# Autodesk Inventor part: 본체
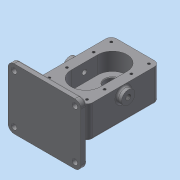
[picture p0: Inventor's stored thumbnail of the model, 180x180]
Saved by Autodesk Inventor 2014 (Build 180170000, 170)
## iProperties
Created: 2026-10
Part Number: 본체
Material: 일반
Document SubType Name: Modeling
Designer: dg
Density: 1 g/cm^3
Appearance: 기본값
Author: dg
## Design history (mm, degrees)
sketch "스케치1"
  geometry: L1 (-40, 60)-(40, 60); L2 (40, 60)-(40, -60); L3 (40, -60)-(-40, -60); L4 (-40, -60)-(-40, 60); L5 (0, 22)-(0, -22); L6 (-24, 22)-(-24, -22); L7 (24, -22)-(24, 22); A1 r 24 centre (0, 22) between (24, 22) and (-24, 22); A2 r 24 centre (0, -22) between (-24, -22) and (24, -22); 4 further points
  constraints: 16 end point, 4 parallel, 4 point on circle, 4 tangent, 3 midpoint, 2 centre point, 1 coincident, 1 horizontal, 1 horizontal alignment, 1 perpendicular, 1 vertical alignment
  dimensions: "d0" = 80 distance of L1.start L1.end; "d1" = 120 distance of L1.end L2.end; "d2" = 44 distance of L5.start L5.end; "d3" = 48 diameter of A1
extrude "돌출1" new body sketch "스케치1" distance "d4" = 53; taper "d5" = 0 deg
extrude "돌출2" cut sketch "스케치1" distance "d6" = 29; taper "d7" = 0 deg
fillet "모깎기1" dims "d8" = 9
sketch "스케치2"
  geometry: L1 (-80, 30)-(-90, 30); L2 (-90, 30)-(-90, -70); L3 (-90, -70)-(-80, -70); L4 (-80, -70)-(-80, 30); L5 (22, -29)-(22, -70); L6 (60, 0)-(-60, 0) reference; L7 (22, -29)-(46, -29) reference; L8 (-22, -29)-(22, -29) reference; L9 (22, -29)-(41, -29); L10 (34.5, -29)-(34.5, -44); L11 (34.5, -44)-(30.5, -44); L12 (30.5, -44)-(30.5, -62.7); L13 (22, -70)-(41, -70); L14 (41, -70)-(41, -29); L15 (30.5, -62.7)-(36, -62.7); L16 (36, -62.7)-(36, -70); L17 (-60, -53)-(-60, 0) reference; L18 (-60, -11.547)-(-80, 0); L19 (-60, -41.453)-(-80, -53); L20 (-22, -29)-(-22, -53); L21 (-51, -53)-(51, -53) reference; L22 (-22, -29)-(-9.5, -29); L23 (-9.5, -29)-(-9.5, -44); L24 (-9.5, -44)-(-22, -44); 1 further point
  constraints: 38 end point, 13 point on line, 9 perpendicular, 5 parallel, 2 horizontal alignment, 1 equal length, 1 horizontal
  dimensions: "d9" = 22 distance from line of point (0, 0) L5; "d10" = 25 diameter of L10 L5; "d11" = 38 diameter of L14 L5; "d12" = 15 distance of L10.start L10.end; "d13" = 17 diameter of L12 L5; "d14" = 28 diameter of L16 L5; "d15" = 7.3 distance of L15.end L16.end; "d16" = 70 distance between parallel lines of L13 L6; "d17" = 10 distance of L1.start L1.end; "d18" = 100 distance of L1.end L2.end; "d19" = 90 distance from line of point (0, 0) L2; "d20" = 53 distance of L19.end L18.end; "d21" = 60 deg angle of L4 L18; "d22" = 17 distance from line of L3 L19.end; "d23" = 44 distance from line of L20 L5.start; "d24" = 25 diameter of L23 L20
revolve "회전1" stored, may be unused: angle "d25" = 90 deg
extrude "돌출3" join sketch "스케치2" stored distance "d26" = 120; taper "d27" = 0 deg
extrude "돌출4" join sketch "스케치2" stored distance "d28" = 48; taper "d29" = 0 deg
revolve "회전2" stored, may be unused: angle "d30" = 90 deg
revolve "회전3" stored, may be unused: angle "d31" = 90 deg
fillet "모깎기2" dims "d32" = 10
hole "구멍1" diameter "d35" = 9; stored, may be unused: countersink angle "d39" = 90 deg, drill point angle "d41" = 118 deg; dims "d33" = 10, "d34" = 10, "d36" = 6, "d37" = 4, "d38" = 2, "d40" = 8
node "작업 평면1"
fillet "모깎기3" dims "d42" = 0.5
chamfer "모따기1" distance "d43" = 0.7; stored, may be unused: second distance "d44" = 2, angle "d45" = 30 deg
node "작업 평면2"
sketch "스케치3"
  geometry: C1 r 11 at (0, -14); 1 further point
  constraints: 1 centre point, 1 vertical alignment
  dimensions: "d47" = 14 distance of point (0, 0) C1.centre; "d48" = 22 diameter of C1
extrude "돌출5" join sketch "스케치3" stored distance "d49" = 48; taper "d50" = 0 deg
hole "구멍2" diameter "d53" = 7.647; stored, may be unused: countersink angle "d59" = 90 deg, drill point angle "d61" = 118 deg; dims "d51" = 10, "d52" = 10, "d54" = 9, "d55" = 0.62479, "d56" = 7.985, "d57" = 4, "d58" = 2, "d60" = 8
fillet "모깎기4" dims "d62" = 3
fillet "모깎기5" dims "d63" = 3
fillet "모깎기6" dims "d64" = 3
fillet "모깎기7" dims "d65" = 3
sketch "스케치4" dims "d0" = 80, "d1" = 120, "d2" = 44, "d3" = 48
  geometry: L1 (100, 0)-(0, 0) reference; L2 (0, 100)-(100, 100) reference; 3 further points
  constraints: 1 midpoint, 1 vertical alignment, 1 other
  dimensions: "d66" = 10 distance from line of L1 point (50, 10)
feature "엠보싱1" sketch "스케치4" dims "d0" = 80, "d1" = 120, "d2" = 44, "d3" = 48, "d67" = 0.5, "d68" = 0
fillet "모깎기8" dims "d69" = 3
sketch "스케치5"
  geometry: A1 r 9 centre (31, 51) between (40, 51) and (31, 60) reference; A2 r 9 centre (-31, 51) between (-31, 60) and (-40, 51) reference; 5 further points
  constraints: 2 coincident, 2 vertical alignment, 1 horizontal alignment
  dimensions: "d70" = 29 distance of point (-31, 22) point (-31, 51)
hole "구멍3" sketch "스케치5" at (-31, 51), (31, 51), (31, 22), (-31, 22) diameter "d71" = 4.134; stored, may be unused: countersink angle "d75" = 82 deg, drill point angle "d77" = 118 deg; dims "d72" = 10, "d73" = 3.023, "d74" = 2, "d76" = 12
chamfer "모따기2" distance "d78" = 1; stored, may be unused: second distance "d79" = 2, angle "d80" = 30 deg
node "솔리드1"
mirror "대칭1"
mirror "대칭2"
mirror "대칭3"
mirror "대칭4"
other parameters: "d46" = 48
